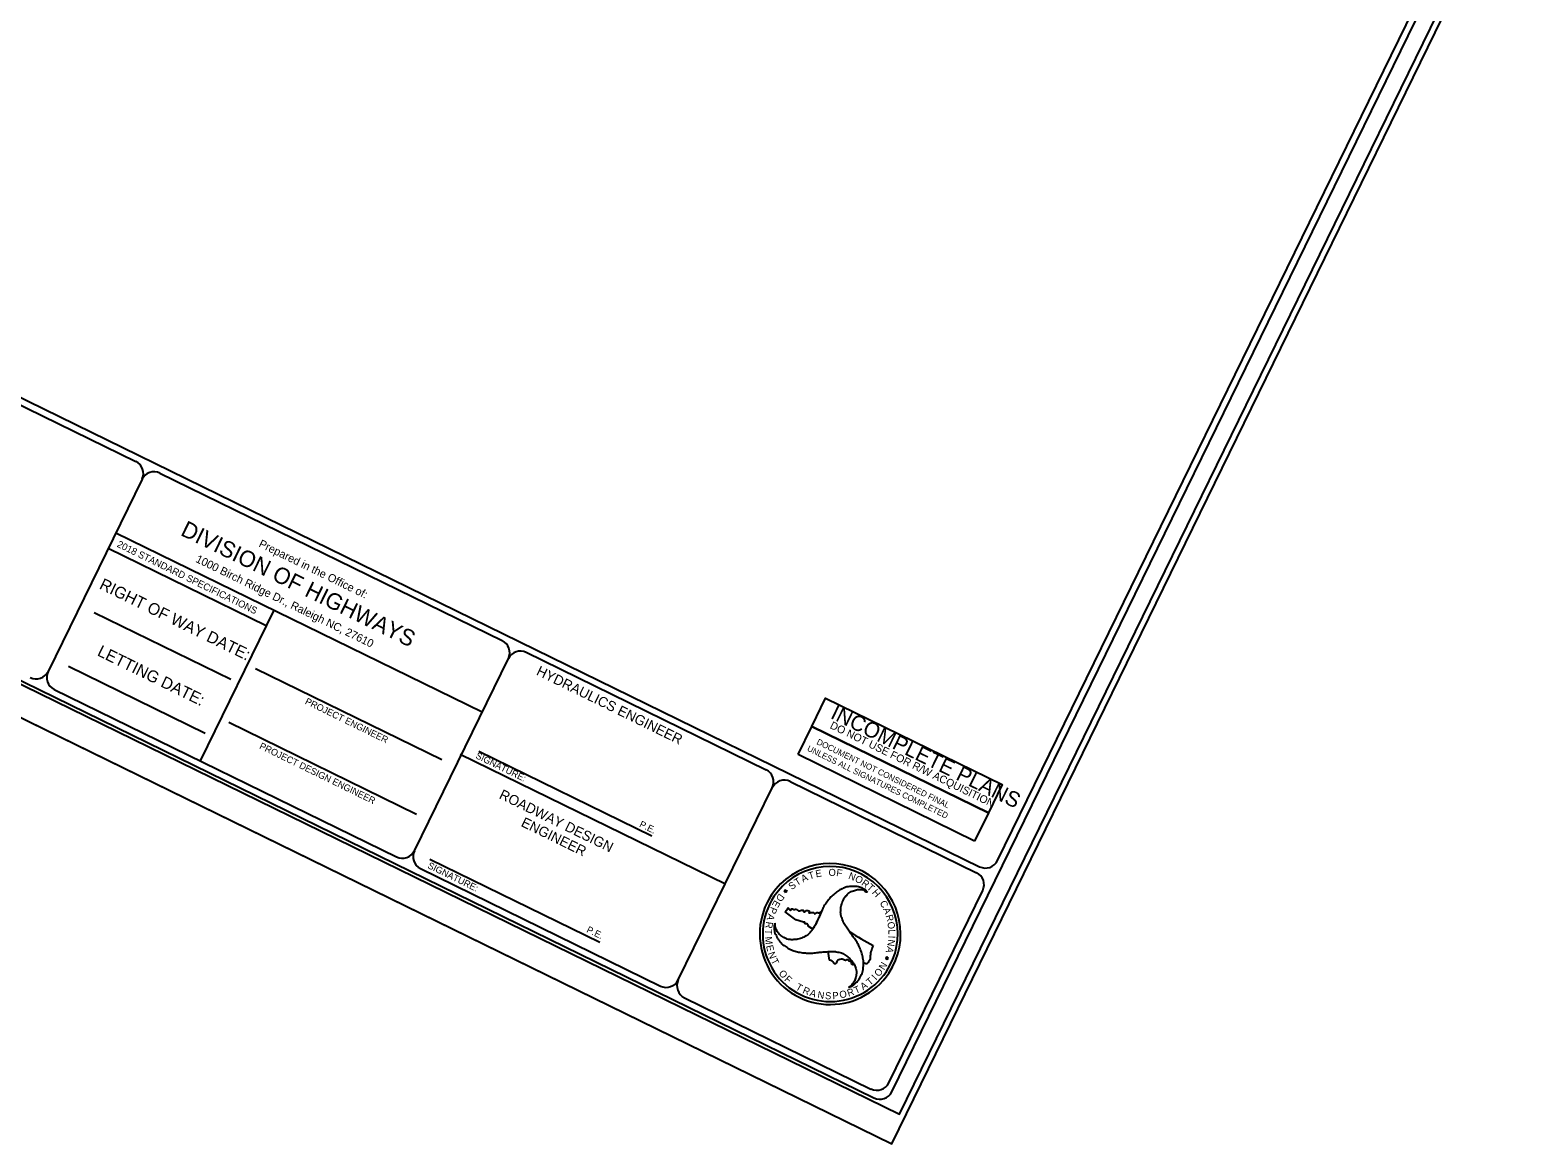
# Model space of a CAD drawing. Extents: x 1517888 to 1526099, y 633375 to 640181.
# Drawn here: x 1521570.5 to 1521683.2, y 636882.4 to 636965.6 of the extents above; entities that cross this region are included whole.
import ezdxf

# ---------------------------------------------------------------- set-up
doc = ezdxf.new("R2010")
doc.units = 0
for name, color, linetype in [('Sheet Cutting Line CELL', 7, 'Continuous'), ('Sheet Plot Border Inside CELL', 7, 'Continuous'), ('Sheet Plot Border Outside CELL', 7, 'Continuous'), ('Sheet Sticker Exception Certification CELL', 7, 'Continuous'), ('Sheet Sticker Incomplete CELL', 7, 'Continuous'), ('Sheet Title CELL', 7, 'Continuous')]:
    doc.layers.add(name, color=color, linetype=linetype)

msp = doc.modelspace()

# ---------------------------------------------------------------- linework, layer by layer
at = {"layer": 'Sheet Cutting Line CELL'}
msp.add_line((1521483.63, 636956.35), (1521634.91, 636882.36), dxfattribs=at)
at = {"layer": 'Sheet Plot Border Inside CELL'}
msp.add_lwpolyline([(1521485.79, 636957.79), (1521635.49, 636884.57), (1521681.85, 636979.36), (1521532.14, 637052.57)], close=True, dxfattribs=at)
at = {"layer": 'Sheet Plot Border Outside CELL'}
msp.add_lwpolyline([(1521683.24, 636981.17), (1521531.96, 637055.16), (1521483.63, 636956.35), (1521634.91, 636882.36)], close=True, dxfattribs=at)
at = {"layer": 'Sheet Sticker Exception Certification CELL'}
for p, q in [((1521627.91, 636911.46), (1521628.94, 636913.57)), ((1521628.94, 636913.57), (1521642.14, 636907.11)), ((1521641.11, 636905), (1521627.91, 636911.46)), ((1521642.14, 636907.11), (1521641.11, 636905))]:
    msp.add_line(p, q, dxfattribs=at)
at = {"layer": 'Sheet Sticker Incomplete CELL'}
msp.add_lwpolyline([(1521628.94, 636913.57), (1521629.97, 636915.68), (1521643.18, 636909.22), (1521642.14, 636907.11)], close=True, dxfattribs=at)
at = {"layer": 'Sheet Title CELL'}
for p, q in [((1521513.92, 636965.47), (1521641.48, 636903.08)), ((1521544.24, 636950.08), (1521578.38, 636933.38)), ((1521578.84, 636932.05), (1521571.81, 636917.67)), ((1521580.18, 636932.51), (1521605.78, 636919.99)), ((1521604.27, 636914.63), (1521576.87, 636928.03)), ((1521588.13, 636921.1), (1521576.31, 636926.88)), ((1521584.72, 636922.77), (1521584.72, 636922.77)), ((1521585.49, 636917.07), (1521575.27, 636922.07)), ((1521588.69, 636922.25), (1521583.19, 636911)), ((1521580.38, 636919.57), (1521580.38, 636919.57)), ((1521599.21, 636904.27), (1521606.24, 636918.65)), ((1521607.57, 636919.11), (1521625.52, 636910.33)), ((1521583.56, 636913.04), (1521573.35, 636918.04)), ((1521587.33, 636917.9), (1521601.27, 636911.09)), ((1521585.32, 636913.88), (1521599.36, 636907.01)), ((1521602.64, 636911.5), (1521622.47, 636901.81)), ((1521604.02, 636911.72), (1521616.98, 636905.38)), ((1521627.32, 636909.45), (1521641.26, 636902.63)), ((1521618.95, 636894.62), (1521625.98, 636908.99)), ((1521600.37, 636903.64), (1521613.08, 636897.43)), ((1521626.86, 636901.21), (1521626.93, 636901.27)), ((1521626.95, 636901.22), (1521626.86, 636901.21)), ((1521626.93, 636901.27), (1521626.9, 636901.35)), ((1521626.9, 636901.35), (1521626.98, 636901.3)), ((1521626.98, 636901.13), (1521626.95, 636901.22)), ((1521626.98, 636901.3), (1521627.04, 636901.36)), ((1521627.01, 636901.22), (1521626.98, 636901.13)), ((1521627.1, 636901.22), (1521627.01, 636901.22)), ((1521627.04, 636901.36), (1521627.02, 636901.27)), ((1521627.02, 636901.27), (1521627.1, 636901.22)), ((1521633.09, 636901.22), (1521633.07, 636901.21)), ((1521633.09, 636901.22), (1521633.07, 636901.21)), ((1521626.94, 636899.7), (1521627.13, 636899.95)), ((1521627.75, 636899.11), (1521626.94, 636899.7)), ((1521628.32, 636898.93), (1521627.75, 636899.11)), ((1521629, 636898.4), (1521628.65, 636898.64)), ((1521631.76, 636898.21), (1521631.76, 636898.21)), ((1521630.26, 636896.09), (1521630.16, 636896.73)), ((1521630.16, 636896.73), (1521630.16, 636896.73)), ((1521634.51, 636896.26), (1521634.44, 636896.2)), ((1521634.44, 636896.2), (1521634.53, 636896.21)), ((1521634.55, 636896.3), (1521634.48, 636896.35)), ((1521634.48, 636896.35), (1521634.51, 636896.26)), ((1521634.53, 636896.21), (1521634.56, 636896.12)), ((1521634.62, 636896.35), (1521634.55, 636896.3)), ((1521634.56, 636896.12), (1521634.59, 636896.21)), ((1521634.59, 636896.21), (1521634.68, 636896.22)), ((1521634.6, 636896.26), (1521634.62, 636896.35)), ((1521634.68, 636896.22), (1521634.6, 636896.26)), ((1521634.7, 636895.13), (1521634.7, 636895.13))]:
    msp.add_line(p, q, dxfattribs=at)
for points in [[(1521634.92, 636886.25), (1521680.17, 636978.78)], [(1521642.82, 636903.54), (1521679.5, 636978.55)], [(1521500.63, 636950.81), (1521633.58, 636885.79)], [(1521572.27, 636916.34), (1521597.87, 636903.81)], [(1521599.67, 636902.94), (1521617.61, 636894.16)], [(1521634.69, 636886.92), (1521641.72, 636901.29)], [(1521619.41, 636893.28), (1521633.35, 636886.46)]]:
    msp.add_lwpolyline(points, dxfattribs=at)
for centre, radius, start, end in [((1521577.94, 636932.49), 1, 333.9377, 63.9377), ((1521579.74, 636931.61), 1, 63.9377, 153.9377), ((1521605.34, 636919.09), 1, 333.9377, 63.9377), ((1521607.14, 636918.21), 1, 63.9377, 153.9377), ((1521570.91, 636918.12), 1, 243.9377, 333.9377), ((1521572.71, 636917.24), 1, 153.9377, 243.9377), ((1521625.08, 636909.43), 1, 333.9377, 63.9377), ((1521626.88, 636908.55), 1, 63.9377, 153.9377), ((1521598.31, 636904.72), 1, 243.9377, 333.9377), ((1521600.11, 636903.84), 1, 153.9377, 243.9377), ((1521641.92, 636903.98), 1, 243.9377, 333.9377), ((1521630.31, 636898.05), 5.27, 326.3589, 146.3589), ((1521630.31, 636898.05), 5.05, 326.3589, 146.3589), ((1521640.82, 636901.74), 1, 333.9377, 63.9377), ((1521630.31, 636898.05), 5.27, 146.3589, 326.3589), ((1521630.31, 636898.05), 5.05, 146.3589, 326.3589), ((1521646.71, 636921.65), 27.79, 232.0373, 232.1369), ((1521646.71, 636921.65), 27.79, 237.4764, 241.6824), ((1521618.05, 636895.06), 1, 243.9377, 333.9377), ((1521619.85, 636894.18), 1, 153.9377, 243.9377), ((1521633.8, 636887.36), 1, 243.9377, 333.9377), ((1521634.02, 636886.69), 1, 243.9377, 333.9377)]:
    msp.add_arc(centre, radius, start, end, dxfattribs=at)
for points in [[(1521633.07, 636901.21), (1521632.99, 636901.31), (1521632.69, 636901.49), (1521632.33, 636901.59), (1521632.3, 636901.59), (1521632.1, 636901.61), (1521631.86, 636901.6), (1521631.47, 636901.54), (1521631.11, 636901.38), (1521630.96, 636901.31), (1521630.81, 636901.2), (1521630.5, 636900.95), (1521630.25, 636900.69), (1521630, 636900.35), (1521629.8, 636900.04), (1521629.64, 636899.69), (1521629.49, 636899.34), (1521629.33, 636899.01), (1521629.16, 636898.66), (1521628.95, 636898.35), (1521628.93, 636898.32), (1521628.66, 636898.02), (1521628.33, 636897.82), (1521627.99, 636897.69), (1521627.81, 636897.65), (1521627.59, 636897.63), (1521627.46, 636897.62), (1521627.19, 636897.65), (1521626.85, 636897.78), (1521626.56, 636897.99), (1521626.35, 636898.23), (1521626.22, 636898.53), (1521626.18, 636898.86)], [(1521631.67, 636894.06), (1521631.78, 636894.09), (1521632.09, 636894.26), (1521632.36, 636894.52), (1521632.38, 636894.54), (1521632.5, 636894.71), (1521632.61, 636894.92), (1521632.75, 636895.29), (1521632.79, 636895.68), (1521632.81, 636895.85), (1521632.79, 636896.04), (1521632.73, 636896.42), (1521632.62, 636896.77), (1521632.46, 636897.16), (1521632.28, 636897.48), (1521632.06, 636897.8), (1521631.84, 636898.1), (1521631.63, 636898.41), (1521631.41, 636898.73), (1521631.24, 636899.06), (1521631.23, 636899.1), (1521631.11, 636899.49), (1521631.1, 636899.88), (1521631.15, 636900.23), (1521631.21, 636900.4), (1521631.31, 636900.61), (1521631.36, 636900.73), (1521631.52, 636900.94), (1521631.81, 636901.18), (1521632.13, 636901.31), (1521632.44, 636901.38), (1521632.77, 636901.34), (1521633.07, 636901.21), (1521633.09, 636901.22)], [(1521627.13, 636899.95), (1521627.13, 636899.99), (1521627.2, 636899.98), (1521627.29, 636899.85), (1521627.38, 636899.86), (1521627.42, 636899.92), (1521627.5, 636899.94), (1521627.58, 636899.87), (1521627.72, 636899.91), (1521627.8, 636899.88), (1521627.95, 636899.78), (1521628.24, 636899.84), (1521628.32, 636899.8), (1521628.31, 636899.75), (1521628.35, 636899.71), (1521628.52, 636899.8), (1521628.55, 636899.81), (1521628.73, 636899.77), (1521628.75, 636899.72), (1521628.71, 636899.65), (1521628.73, 636899.62), (1521628.79, 636899.63), (1521628.91, 636899.66), (1521629.06, 636899.65), (1521629.18, 636899.55), (1521629.27, 636899.64), (1521629.49, 636899.64), (1521629.56, 636899.68), (1521629.61, 636899.74)], [(1521628.65, 636898.64), (1521628.66, 636898.72), (1521628.61, 636898.79), (1521628.49, 636898.8), (1521628.42, 636898.85), (1521628.38, 636898.95), (1521628.32, 636898.93)], [(1521629.65, 636899.7), (1521629.64, 636899.69), (1521629.49, 636899.34), (1521629.33, 636899.01), (1521629.16, 636898.66), (1521629, 636898.4)], [(1521626.18, 636898.86), (1521626.14, 636898.74), (1521626.13, 636898.39), (1521626.22, 636898.03), (1521626.24, 636898), (1521626.32, 636897.81), (1521626.45, 636897.61), (1521626.7, 636897.31), (1521627.02, 636897.08), (1521627.15, 636896.98), (1521627.33, 636896.9), (1521627.69, 636896.76), (1521628.04, 636896.68), (1521628.46, 636896.63), (1521628.82, 636896.61), (1521629.21, 636896.65), (1521629.59, 636896.69), (1521629.96, 636896.72), (1521630.35, 636896.74), (1521630.72, 636896.73), (1521630.76, 636896.72), (1521631.16, 636896.63), (1521631.49, 636896.44), (1521631.77, 636896.22), (1521631.9, 636896.08), (1521632.02, 636895.9), (1521632.1, 636895.79), (1521632.21, 636895.55), (1521632.27, 636895.18), (1521632.23, 636894.83), (1521632.12, 636894.52), (1521631.93, 636894.26), (1521631.67, 636894.06)], [(1521632.81, 636895.92), (1521632.79, 636896.04), (1521632.73, 636896.42), (1521632.62, 636896.77), (1521632.46, 636897.16), (1521632.28, 636897.48), (1521632.06, 636897.8), (1521631.84, 636898.1), (1521631.76, 636898.21)], [(1521630.16, 636896.73), (1521630.35, 636896.74), (1521630.72, 636896.73), (1521630.76, 636896.72), (1521631.16, 636896.63), (1521631.49, 636896.44), (1521631.77, 636896.22), (1521631.9, 636896.08), (1521632.02, 636895.9), (1521632.1, 636895.8)], [(1521633.52, 636897.18), (1521633.39, 636896.84), (1521633.31, 636896.4), (1521633.29, 636896.14), (1521633.18, 636895.98), (1521633.01, 636895.81), (1521632.81, 636895.92)], [(1521632.1, 636895.8), (1521632, 636895.75), (1521631.93, 636895.79), (1521631.88, 636895.96), (1521631.72, 636896.02), (1521631.68, 636896.1), (1521631.64, 636896.13), (1521631.45, 636896.07), (1521631.29, 636896.14), (1521630.95, 636896.12), (1521630.84, 636896.05), (1521630.71, 636895.83), (1521630.63, 636895.83), (1521630.57, 636895.88), (1521630.46, 636896.03), (1521630.26, 636896.09)]]:
    msp.add_spline(points, degree=3, dxfattribs=at)

# ---------------------------------------------------------------- texts
at = {"layer": 'Sheet Sticker Exception Certification CELL'}
for s, p in [('DOCUMENT NOT CONSIDERED FINAL', (1521629.25, 636912.26)), ('UNLESS ALL SIGNATURES COMPLETED', (1521628.54, 636911.77))]:
    msp.add_text(s, height=0.45, rotation=333.9377, dxfattribs=at).set_placement(p)
at = {"layer": 'Sheet Sticker Incomplete CELL'}
for s, height, p in [('INCOMPLETE PLANS', 1.152, (1521630.26, 636914.22)), ('DO NOT USE FOR R/W ACQUISITION', 0.576, (1521630.24, 636913.46))]:
    msp.add_text(s, height=height, rotation=333.9377, dxfattribs=at).set_placement(p)
at = {"layer": 'Sheet Title CELL'}
for s, height, rotation, p in [('DIVISION OF HIGHWAYS', 1.2187, 333.9377, (1521581.65, 636927.9)), ('2018 STANDARD SPECIFICATIONS', 0.52, 333.9377, (1521576.92, 636927.02)), ('Prepared in the Office of:', 0.5999, 333.9377, (1521587.52, 636927.03)), ('1000 Birch Ridge Dr., Raleigh NC, 27610', 0.6, 333.9377, (1521582.8, 636925.89)), ('RIGHT OF WAY DATE: ', 0.875, 333.9377, (1521575.58, 636923.9)), ('LETTING DATE:', 0.875, 333.9377, (1521575.43, 636918.9)), (' HYDRAULICS ENGINEER', 0.75, 333.9377, (1521608.02, 636917.58)), ('PROJECT ENGINEER', 0.4999, 333.9377, (1521590.99, 636915.28)), ('PROJECT DESIGN ENGINEER', 0.4999, 333.9377, (1521587.57, 636911.94)), ('SIGNATURE:', 0.5, 333.9377, (1521603.74, 636911.22)), ('ROADWAY DESIGN', 0.7499, 333.9377, (1521605.49, 636908.22)), ('ENGINEER', 0.75, 333.9377, (1521607.13, 636906.14)), ('P.E.', 0.5, 333.9377, (1521615.99, 636906.09)), ('SIGNATURE:', 0.5, 333.9377, (1521600.16, 636903)), ('T', 0.527, 31.739, (1521627.83, 636901.63)), ('A', 0.527, 24.6866, (1521628.27, 636901.9)), ('T', 0.524, 17.6314, (1521628.77, 636902.12)), ('E', 0.524, 10.5158, (1521629.26, 636902.28)), ('O', 0.526, 358.5764, (1521630.18, 636902.4)), ('F', 0.527, 351.4296, (1521630.74, 636902.39)), ('N', 0.526, 339.3426, (1521631.63, 636902.2)), ('O', 0.527, 331.8445, (1521632.11, 636902.02)), ('S', 0.525, 38.1151, (1521627.44, 636901.32)), ('R', 0.526, 325.2346, (1521632.6, 636901.75)), ('T', 0.527, 318.585, (1521633.01, 636901.47)), ('H', 0.525, 311.5002, (1521633.4, 636901.12)), ('P', 0.526, 248.0321, (1521625.89, 636900.12)), ('E', 0.523, 240.4997, (1521626.16, 636900.62)), ('D', 0.526, 234.2119, (1521626.51, 636901.12)), ('C', 0.524, 299.1579, (1521633.99, 636900.38)), ('R', 0.526, 261.6933, (1521625.52, 636899)), ('A', 0.525, 254.6247, (1521625.68, 636899.6)), ('A', 0.525, 291.6609, (1521634.25, 636899.92)), ('R', 0.525, 285.2969, (1521634.45, 636899.42)), ('O', 0.527, 278.1773, (1521634.58, 636898.93)), ('P.E.', 0.5, 333.9377, (1521612.04, 636898.21)), ('T', 0.525, 268.3439, (1521625.44, 636898.42)), ('M', 0.524, 275.5789, (1521625.43, 636897.83)), ('L', 0.524, 271.9436, (1521634.66, 636898.38)), ('I', 0.526, 267.9543, (1521634.66, 636897.93)), ('E', 0.524, 283.0457, (1521625.51, 636897.16)), ('N', 0.527, 290.0172, (1521625.64, 636896.61)), ('A', 0.526, 254.8222, (1521634.58, 636897.16)), ('N', 0.525, 262.2542, (1521634.65, 636897.67)), ('T', 0.525, 296.8592, (1521625.85, 636896.06)), ('N', 0.526, 58.567, (1521634.35, 636895.31)), ('O', 0.525, 310.1629, (1521626.42, 636895.09)), ('F', 0.525, 317.3282, (1521626.84, 636894.61)), ('T', 0.524, 330.2374, (1521627.68, 636893.94)), ('A', 0.527, 33.449, (1521632.77, 636893.83)), ('T', 0.525, 40.5334, (1521633.28, 636894.17)), ('I', 0.527, 46.1833, (1521633.73, 636894.56)), ('O', 0.524, 51.319, (1521633.96, 636894.81)), ('R', 0.526, 337.194, (1521628.2, 636893.65)), ('A', 0.524, 343.9471, (1521628.73, 636893.43)), ('N', 0.524, 350.9788, (1521629.33, 636893.27)), ('S', 0.523, 358.1892, (1521629.92, 636893.18)), ('P', 0.525, 5.3811, (1521630.5, 636893.17)), ('O', 0.527, 12.0731, (1521631.06, 636893.23)), ('R', 0.526, 19.2622, (1521631.68, 636893.36)), ('T', 0.524, 25.362, (1521632.23, 636893.56))]:
    msp.add_text(s, height=height, rotation=rotation, dxfattribs=at).set_placement(p)

doc.saveas('drawing.dxf')
